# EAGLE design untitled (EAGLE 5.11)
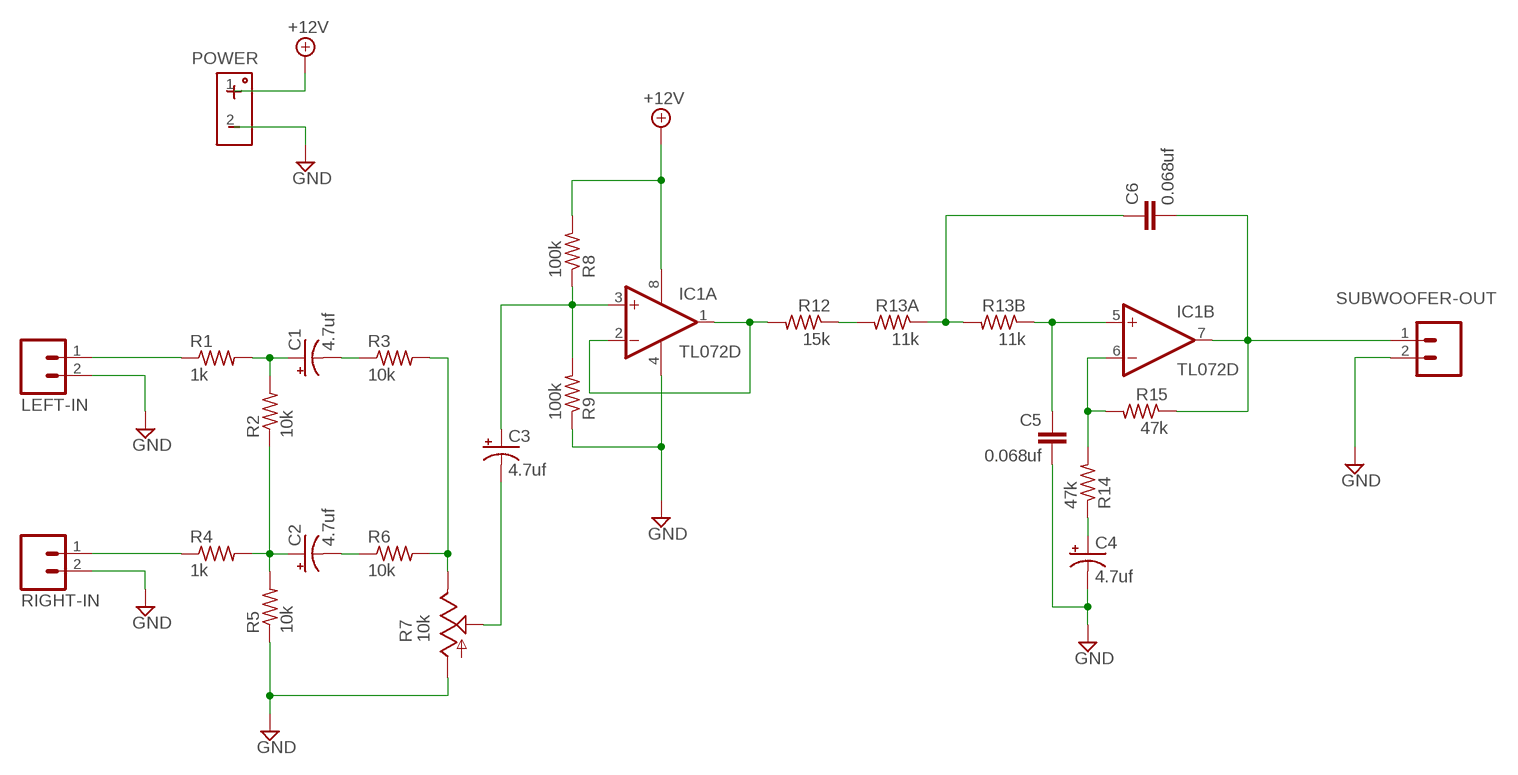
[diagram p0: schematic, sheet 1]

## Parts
C1  4.7uf  CPOL-USC  [PANASONIC_C]
C2  4.7uf  CPOL-USC  [PANASONIC_C]
C3  4.7uf  CPOL-USC  [PANASONIC_C]
C4  4.7uf  CPOL-USC  [PANASONIC_C]
C5  0.068uf  C-EUC0805  [C0805]
C6  0.068uf  C-EUC0805  [C0805]
IC1  TL072D  [SO08]
LEFT-IN  M02LOCK  [1X02_LOCK]
POWER  HEADER-POWER  [HEADER-POWER]
R1  1k  R-US_M0805  [M0805]
R2  10k  R-US_M0805  [M0805]
R3  10k  R-US_M0805  [M0805]
R4  1k  R-US_M0805  [M0805]
R5  10k  R-US_M0805  [M0805]
R6  10k  R-US_M0805  [M0805]
R7  10k  POT-TRIM-0.35IN  [POT-TRIM-0.35IN]
R8  100k  R-US_M0805  [M0805]
R9  100k  R-US_M0805  [M0805]
R12  15k  R-US_M1206  [M1206]
R13A  11k  R-US_M0805  [M0805]
R13B  11k  R-US_M0805  [M0805]
R14  47k  R-US_M0805  [M0805]
R15  47k  R-US_M0805  [M0805]
RIGHT-IN  M02LOCK  [1X02_LOCK]
SUBWOOFER-OUT  M02LOCK  [1X02_LOCK]

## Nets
+12V: IC1.8(P:V+) POWER.1 R8.2
GND: C4.- C5.2 IC1.4(P:V-) LEFT-IN.2 POWER.2 R5.1 R7.1(A) R9.1 RIGHT-IN.2 SUBWOOFER-OUT.2
N$1: C2.+ R2.1 R4.2 R5.2
N$2: C1.+ R1.2 R2.2
N$3: C1.- R3.1
N$4: C2.- R6.1
N$5: R3.2 R6.2 R7.3(E)
N$6: LEFT-IN.1 R1.1
N$7: R4.1 RIGHT-IN.1
N$8: C3.+ IC1.3(A:+IN) R8.1 R9.2
N$9: C3.- R7.2(S)
N$10: C6.1 R13A.1 R13B.2
N$11: R12.1 R13A.2
N$12: IC1.1(A:OUT) IC1.2(A:-IN) R12.2
N$13: IC1.6(B:-IN) R14.2 R15.2
N$14: C4.+ R14.1
N$16: C5.1 IC1.5(B:+IN) R13B.1
N$17: C6.2 IC1.7(B:OUT) R15.1 SUBWOOFER-OUT.1

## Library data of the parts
C1-C4 = rcl:CPOL-US: POLARIZED CAPACITOR, American symbol
C5 C6 = rcl:C-EU: CAPACITOR, European symbol
IC1 = linear:TL072: OP AMP
LEFT-IN RIGHT-IN SUBWOOFER-OUT = SparkFun:M02: Header 2
POWER = trl:HEADER-POWER
R1-R6 R8 R9 R12 R13A R13B R14 R15 = resistor:R-US_: RESISTOR, American symbol
R7 = trl:POT-TRIM-0.35IN

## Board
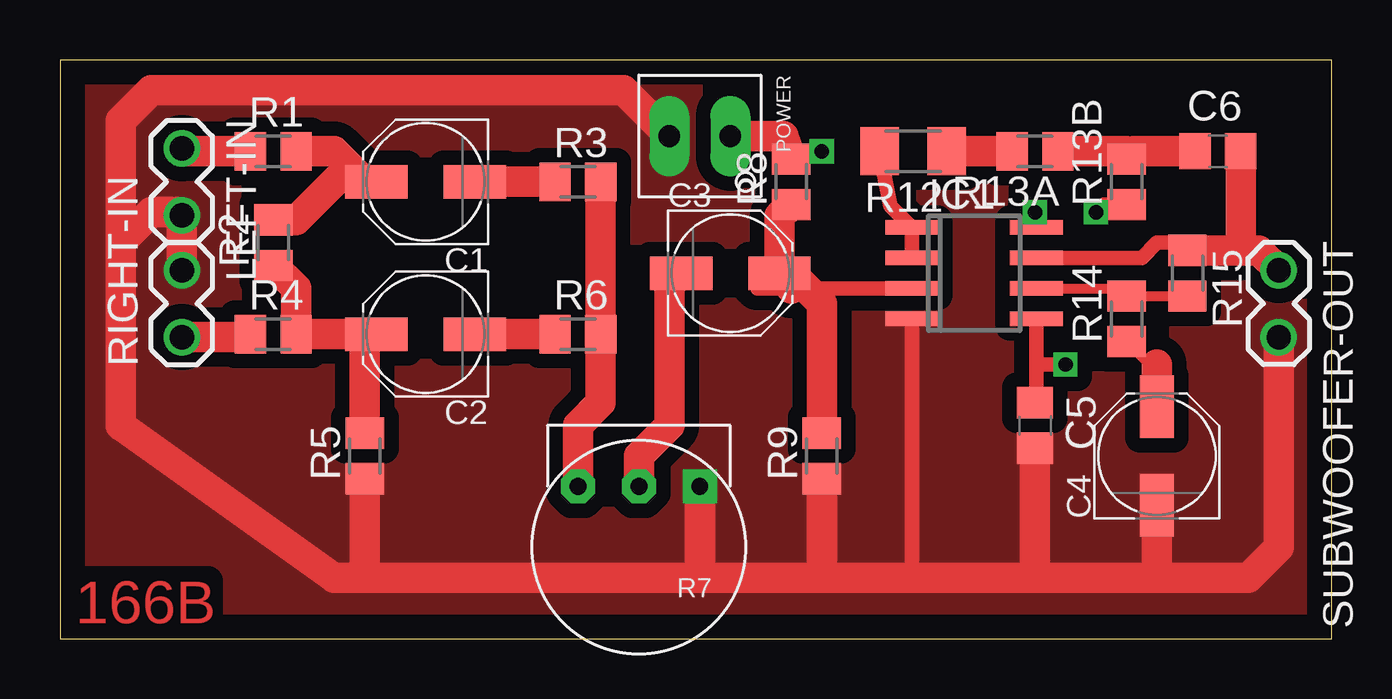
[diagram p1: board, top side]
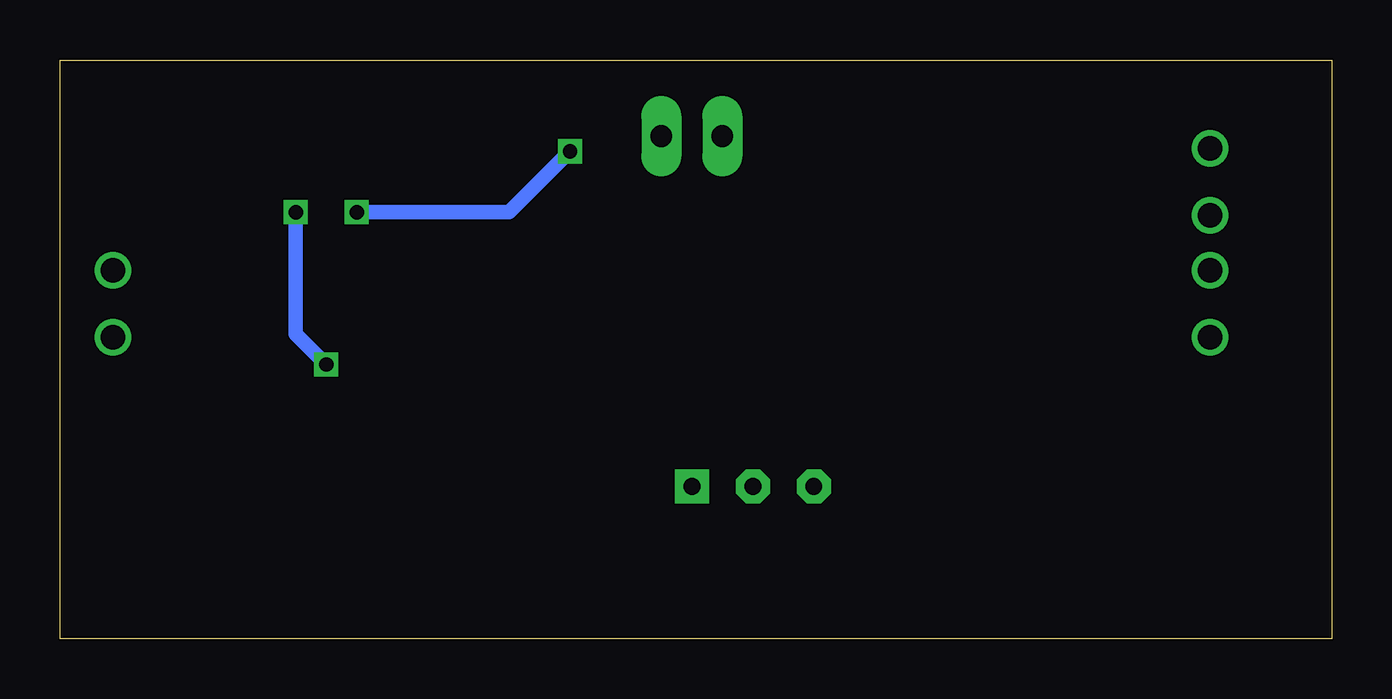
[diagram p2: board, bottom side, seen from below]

Size 53.01 x 24.12 mm. Coordinates in mm from the lower left corner, seen from the top.
Outline: 0,0 53.01,0 53.01,24.12 0,24.12 0,0
Copper layers (1*16): Top 0.035mm / dielectric 1.5mm / Bottom 0.035mm
Design rules "default": minimum track width 10mil, minimum drill 0.6mm, track to track 8mil, track to pad 8mil, pad to pad 8mil, via to via 8mil, smd to smd 8mil, copper to edge 40mil, drill to drill 8mil, minimum pad ring 10mil, minimum via ring 8mil, stop-mask expansion 4mil, vias tented up to drill 0mil, thermal gap 10mil

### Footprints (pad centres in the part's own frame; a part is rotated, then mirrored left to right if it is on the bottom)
PANASONIC_C = smd 2.6 x 1.4: + 2.05,0; - -2.05,0
C0805 = smd 1.3 x 1.5: 1 -0.95,0; 2 0.95,0
SO08 = smd 0.6 x 2.2: 1 -1.905,-2.6; 2 -0.635,-2.6; 3 0.635,-2.6; 4 1.905,-2.6; 5 1.905,2.6; 6 0.635,2.6; 7 -0.635,2.6; 8 -1.905,2.6
1X02_LOCK = drill 1.016 round: 1 -0.127,0; 2 2.667,0
HEADER-POWER = drill 0.9 pad 1.676 long: 1 0,1.27; 2 0,-1.27
M0805 = smd 1.3 x 1.6: 1 -0.95,0; 2 0.95,0
POT-TRIM-0.35IN = drill 0.7 pad 1.422 square: 1 -2.54,-3.81 | drill 0.7 pad 1.422 octagon: 2 0,-3.81; 3 2.54,-3.81
M1206 = smd 1.6 x 2: 1 -1.4,0; 2 1.4,0

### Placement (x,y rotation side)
C1  15.24,19.05 180 top
C2  15.24,12.7 180 top
C3  27.94,15.24 0 top
C4  45.72,7.62 90 top
C5  40.64,8.89 270 top
C6  48.26,20.32 0 top
IC1  38.1,15.24 270 top
LEFT-IN  5.08,20.32 270 top
POWER  26.67,20.95 270 top
R1  8.89,20.32 0 top
R2  8.89,16.51 90 top
R3  21.59,19.05 0 top
R4  8.89,12.7 0 top
R5  12.7,7.62 90 top
R6  21.59,12.7 0 top
R7  24.13,2.54 180 top
R8  30.48,19.05 90 top
R9  31.75,7.62 90 top
R12  35.56,20.32 180 top
R13A  40.64,20.32 180 top
R13B  44.45,19.05 90 top
R14  44.45,13.34 90 top
R15  46.99,15.24 270 top
RIGHT-IN  5.08,12.7 90 top
SUBWOOFER-OUT  50.8,15.24 270 top

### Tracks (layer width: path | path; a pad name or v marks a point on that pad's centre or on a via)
+12V  (via drill 0.6)
  Top 0.61: IC1.8 40.7,17.72 v40.64,17.78 | v31.75,20.32 30.8,20.32 R8.2
  Top 1.27: POWER.1 30.16,20.95 R8.2
  Bottom 0.61: v40.64,17.78 34.29,17.78 v31.75,20.32
GND
  Top 0.406: RIGHT-IN.2 5.21,15.37
  Top 0.61: IC1.4 35.5,2.6 35.56,2.54
  Top 1.27: 12.7,2.54 11.43,2.54 2.54,8.89 2.54,16.51 | 12.7,2.54 26.67,2.54 | 26.67,2.54 31.75,2.54 | 31.75,2.54 35.56,2.54 40.64,2.54 | 40.64,2.54 45.72,2.54 | 45.72,2.54 49.53,2.54 50.8,3.81 SUBWOOFER-OUT.2 | 45.72,2.54 C4.- | 40.64,2.54 C5.2 | RIGHT-IN.2 LEFT-IN.2 5.08,17.78 3.81,17.78 2.54,16.51 | 12.7,2.54 R5.1 | 26.67,2.54 R7.1 | 31.75,2.54 R9.1 | POWER.2 23.5,22.86 3.81,22.86 2.54,21.59 2.54,16.51
  pour Top (isolate 0.61, no thermals): 0,24.13 53.34,24.13 53.34,0 0,0
N$1
  Top 1.27: R2.1 9.84,14.61 R4.2 12.7,12.7 | 12.7,12.7 C2.+ | 12.7,12.7 R5.2
N$2
  Top 1.27: C1.+ 12.7,19.05 12.06,19.68 | 12.06,19.68 11.43,20.32 R1.2 | R2.2 9.84,17.46 12.06,19.68
N$3
  Top 1.27: C1.- R3.1
N$4
  Top 1.27: C2.- R6.1
N$5
  Top 1.27: R3.2 R6.2 22.54,9.84 21.59,8.89 R7.3
N$6
  Top 1.27: R1.1 5.21,20.32 LEFT-IN.1
N$7
  Top 1.27: RIGHT-IN.1 7.81,12.57 R4.1
N$8
  Top 0.406: 29.07,14.61 C3.+
  Top 0.61: 29.07,14.61 30.48,14.61 IC1.3
  Top 1.27: C3.+ 29.99,17.61 R8.1 | R9.2 31.75,13.97 30.48,15.24 30.48,14.61
N$9
  Top 1.27: R7.2 24.13,7.62 25.4,8.89 25.4,14.75 C3.-
N$10
  Top 0.61: 44.45,20.32 R13B.2
  Top 1.27: C6.1 44.77,20.32 R13B.2 | R13A.1 44.45,20.32
N$11
  Top 1.27: R12.1 R13A.2
N$12
  Top 0.61: IC1.2 IC1.1 34.61,18.04 R12.2
N$13
  Top 0.406: IC1.6 44.45,14.61 R14.2 R15.2
N$14
  Top 0.406: 45.72,11.43 45.41,11.43 R14.1
  Top 1.27: C4.+ 45.72,11.43
N$16  (via drill 0.6)
  Top 0.61: 40.7,11.43 40.7,9.9 C5.1 | 40.7,11.43 IC1.5 | R13B.1 43.5,18.1 v43.18,17.78 | 40.7,11.43 v41.91,11.43
  Bottom 0.61: v43.18,17.78 43.18,12.7 v41.91,11.43
N$17
  Top 0.61: IC1.7 45.09,15.88 45.72,16.51 46.67,16.51 R15.1
  Top 1.27: R15.1 49.53,16.19 | 49.53,16.19 49.98,16.19 SUBWOOFER-OUT.1 | C6.2 49.21,16.51 49.53,16.19

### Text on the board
Top: 166B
